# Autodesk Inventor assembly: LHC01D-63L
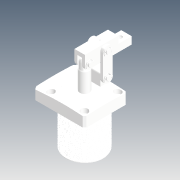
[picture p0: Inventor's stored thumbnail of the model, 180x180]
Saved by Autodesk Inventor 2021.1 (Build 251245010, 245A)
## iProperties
Created: 2019-04
Part Number: LHC01D-63L
Description: STEP AP214
Document SubType Name: Assembly
Designer: user
Title: LHC01D-63L.STEP
Revision Number: ÈÎºÎ
Sending System: SolidWorks 2016
Preprocessor: SwSTEP 2.0
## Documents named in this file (12)
- D:\Vault_2016\Projekty\Clamptek\Hydraulic\LHC01D\Inventor\LHC01D-63L\LHC01D-63L.iam
- D:\Vault_2016\Projekty\Clamptek\Hydraulic\LHC01D\Inventor\LHC01D-63L\LHC01D-63-01_1.ipt
- D:\Vault_2016\Projekty\Clamptek\Hydraulic\LHC01D\Inventor\LHC01D-63L\CPLCU-50-08_4.ipt
- D:\Vault_2016\Projekty\Clamptek\Hydraulic\LHC01D\Inventor\LHC01D-63L\CPLCU-63-01_1.ipt
- D:\Vault_2016\Projekty\Clamptek\Hydraulic\LHC01D\Inventor\LHC01D-63L\CPLCU-63-02_1.ipt
- D:\Vault_2016\Projekty\Clamptek\Hydraulic\LHC01D\Inventor\LHC01D-63L\CPLCU-63-03_1.ipt
- D:\Vault_2016\Projekty\Clamptek\Hydraulic\LHC01D\Inventor\LHC01D-63L\CPLCU-63-04_1.ipt
- D:\Vault_2016\Projekty\Clamptek\Hydraulic\LHC01D\Inventor\LHC01D-63L\CPLCU-63-05_1.ipt
- D:\Vault_2016\Projekty\Clamptek\Hydraulic\LHC01D\Inventor\LHC01D-63L\LHC01D-63-07_1.ipt
- D:\Vault_2016\Projekty\Clamptek\Hydraulic\LHC01D\Inventor\LHC01D-63L\M4ningjin_9.ipt
- D:\Vault_2016\Projekty\Clamptek\Hydraulic\LHC01D\Inventor\LHC01D-63L\¶ÂÍ·_14.ipt
- D:\Vault_2016\Projekty\Clamptek\Hydraulic\LHC01D\Inventor\LHC01D-63L\LHC01D63»îÈû¸Ë.ipt
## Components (25 placed, 25 different names)
1. LHC01D-63-01_1_1
2. CPLCU-50-08_4_2
3. CPLCU-63-01_1_3
4. CPLCU-63-02_1_4
5. CPLCU-63-03_1_5
6. CPLCU-63-04_1_6
7. CPLCU-63-05_1_7
8. LHC01D-63-07_1_8
9. CPLCU-63-02_1_9
10. CPLCU-63-04_1_10
11. LHC01D-63-07_1_11
12. LHC01D-63-07_1_12
13. LHC01D-63-07_1_13
14. LHC01D-63-07_1_14
15. LHC01D-63-07_1_15
16. CPLCU-50-08_4_16
17. CPLCU-50-08_4_17
18. CPLCU-50-08_4_18
19. CPLCU-50-08_4_19
20. CPLCU-50-08_4_20
21. M4ningjin_9_21
22. ¶ÂÍ·_14_22
23. ¶ÂÍ·_14_23
24. M4ningjin_9_24
25. LHC01D63»îÈû¸Ë_25
